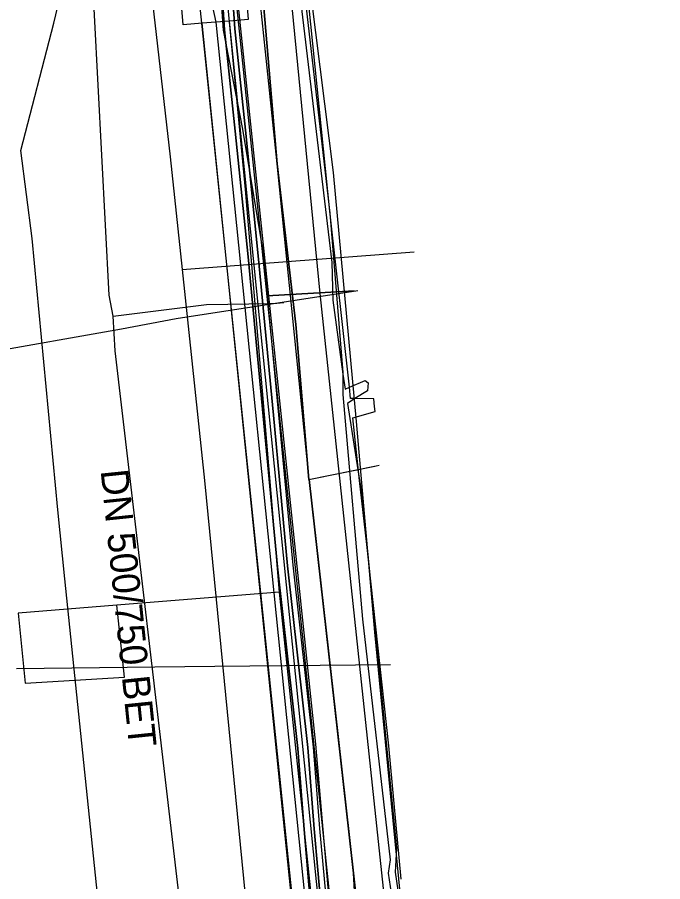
# Model space of a CAD drawing. Extents: x -600309 to -598967, y -1161267 to -1160292.
# Drawn here: x -599156.43 to -599137.72, y -1160334.81 to -1160309.76 of the extents above; entities that cross this region are included whole.
import ezdxf

# ---------------------------------------------------------------- set-up
doc = ezdxf.new("R2010")
doc.units = 0
for name, color, linetype in [('Vrstva 10', 7, 'Continuous'), ('Vrstva 12', 7, 'Continuous'), ('Vrstva 13', 7, 'Continuous'), ('Vrstva 16', 7, 'Continuous'), ('Vrstva 42', 7, 'Continuous'), ('Vrstva 44', 7, 'Continuous'), ('Vrstva 54', 7, 'Continuous'), ('Vrstva 55', 7, 'Continuous'), ('Vrstva 58', 7, 'Continuous'), ('Vrstva 9', 7, 'Continuous')]:
    doc.layers.add(name, color=color, linetype=linetype)

msp = doc.modelspace()

# ---------------------------------------------------------------- linework, layer by layer
at = {"layer": 'Vrstva 10'}
for points in [[(-599152.66, -1160306.2), (-599152.69, -1160305.8), (-599150.08, -1160305.59), (-599149.73, -1160309.82), (-599150.28, -1160309.87)], [(-599151.07, -1160309.93), (-599151.62, -1160309.98), (-599151.8, -1160307.73), (-599152.59, -1160307), (-599152.61, -1160306.75)], [(-599150.28, -1160309.87), (-599151.07, -1160309.93)], [(-599140.7, -1160404.55), (-599150.28, -1160309.87)], [(-599141.4, -1160404.61), (-599151.07, -1160309.93)]]:
    msp.add_lwpolyline(points, dxfattribs=at)
at = {"layer": 'Vrstva 12'}
for points in [[(-599151.44, -1160306.36), (-599150.67, -1160309.9), (-599141.05, -1160404.58), (-599141.12, -1160405.96)], [(-599147.98, -1160323.16), (-599148.35, -1160318.66), (-599148.89, -1160314.01), (-599149.67, -1160306.58)], [(-599147.98, -1160323.16), (-599146.02, -1160322.76), (-599145.94, -1160322.74)], [(-599147.98, -1160323.16), (-599146.69, -1160334.57)], [(-599146.69, -1160334.57), (-599146.63, -1160335.61)]]:
    msp.add_lwpolyline(points, dxfattribs=at)
at = {"layer": 'Vrstva 13'}
for points in [[(-599153.787, -1160295.927), (-599153.482, -1160299.417), (-599153.105, -1160304.16), (-599153.022, -1160304.852), (-599151.992, -1160313.802), (-599151.646, -1160317.07), (-599150.999, -1160323.182), (-599149.825, -1160335.213), (-599149.473, -1160338.732), (-599148.636, -1160347.089), (-599147.954, -1160353.159), (-599147.238, -1160360.509), (-599146.807, -1160364.97), (-599146.176, -1160371.033), (-599145.433, -1160378.125), (-599143.657, -1160395.093), (-599143.103, -1160401.117), (-599142.921, -1160402.361), (-599142.679, -1160404.01), (-599144.473, -1160407.034), (-599142.877, -1160426.561)], [(-599151.646, -1160317.07), (-599151.4, -1160317.051), (-599144.921, -1160316.559)]]:
    msp.add_lwpolyline(points, dxfattribs=at)
at = {"layer": 'Vrstva 16'}
for points in [[(-599147.21, -1160376.02), (-599147.47, -1160373.8), (-599149.64, -1160353.99), (-599149.67, -1160353.23), (-599149.85, -1160352.21), (-599151.43, -1160337.13), (-599151.65, -1160336.05), (-599151.74, -1160335.16), (-599153.59, -1160319.43), (-599153.65, -1160318.42), (-599153.76, -1160317.81), (-599154.72, -1160299.54), (-599152.95, -1160297.98), (-599152.73, -1160297.71), (-599147.093, -1160292.347)], [(-599153.65, -1160318.42), (-599150.94, -1160318.08), (-599149.1, -1160318.06), (-599149.01, -1160318.06), (-599148.7, -1160318.03)]]:
    msp.add_lwpolyline(points, dxfattribs=at)
at = {"layer": 'Vrstva 42'}
for points in [[(-599147.909, -1160335.706), (-599148.116, -1160333.305), (-599148.299, -1160330.954), (-599148.889, -1160325.685), (-599149.299, -1160321.324), (-599149.739, -1160316.705), (-599150.109, -1160313.065), (-599150.419, -1160310.123), (-599150.541, -1160308.353), (-599150.307, -1160306.898), (-599149.897, -1160305.408), (-599149.671, -1160303.974), (-599149.758, -1160302.868), (-599150.029, -1160301.98), (-599150.661, -1160300.875), (-599150.902, -1160299.819), (-599150.738, -1160298.282), (-599150.299, -1160296.681), (-599149.513, -1160295.331), (-599148.572, -1160293.268), (-599147.982, -1160292.347)], [(-599147.909, -1160335.706), (-599148.116, -1160333.305), (-599148.299, -1160330.954), (-599148.889, -1160325.685), (-599149.299, -1160321.324), (-599149.739, -1160316.705), (-599150.109, -1160313.065), (-599150.419, -1160310.123), (-599150.541, -1160308.353), (-599150.307, -1160306.898), (-599149.897, -1160305.408), (-599149.671, -1160303.974), (-599149.758, -1160302.868), (-599150.029, -1160301.98), (-599150.661, -1160300.875), (-599150.902, -1160299.819), (-599150.738, -1160298.282), (-599150.299, -1160296.681), (-599149.513, -1160295.331), (-599148.572, -1160293.268), (-599147.982, -1160292.347)], [(-599147.982, -1160292.347), (-599148.572, -1160293.268), (-599149.513, -1160295.331), (-599150.299, -1160296.681), (-599150.738, -1160298.282), (-599150.902, -1160299.819), (-599150.661, -1160300.875), (-599150.029, -1160301.98), (-599149.758, -1160302.868), (-599149.671, -1160303.974), (-599149.897, -1160305.408), (-599150.307, -1160306.898), (-599150.541, -1160308.353), (-599150.419, -1160310.123), (-599150.109, -1160313.065), (-599149.739, -1160316.705), (-599149.299, -1160321.324), (-599148.889, -1160325.685), (-599148.299, -1160330.954), (-599148.116, -1160333.305), (-599147.909, -1160335.706)], [(-599147.982, -1160292.347), (-599148.572, -1160293.268), (-599149.513, -1160295.331), (-599150.299, -1160296.681), (-599150.738, -1160298.282), (-599150.902, -1160299.819), (-599150.661, -1160300.875), (-599150.029, -1160301.98), (-599149.758, -1160302.868), (-599149.671, -1160303.974), (-599149.897, -1160305.408), (-599150.307, -1160306.898), (-599150.541, -1160308.353), (-599150.419, -1160310.123), (-599150.109, -1160313.065), (-599149.739, -1160316.705), (-599149.299, -1160321.324), (-599148.889, -1160325.685), (-599148.299, -1160330.954), (-599148.116, -1160333.305), (-599147.909, -1160335.706)], [(-599147.611, -1160335.674), (-599147.818, -1160333.281), (-599148.001, -1160330.926), (-599148.591, -1160325.655), (-599149.001, -1160321.296), (-599149.441, -1160316.675), (-599149.811, -1160313.035), (-599150.121, -1160310.097), (-599150.239, -1160308.367), (-599150.013, -1160306.962), (-599149.603, -1160305.472), (-599149.369, -1160303.986), (-599149.462, -1160302.812), (-599149.751, -1160301.86), (-599150.379, -1160300.765), (-599150.598, -1160299.801), (-599150.442, -1160298.338), (-599150.021, -1160296.799), (-599149.247, -1160295.469), (-599148.308, -1160293.412), (-599147.626, -1160292.347)], [(-599147.611, -1160335.674), (-599147.818, -1160333.281), (-599148.001, -1160330.926), (-599148.591, -1160325.655), (-599149.001, -1160321.296), (-599149.441, -1160316.675), (-599149.811, -1160313.035), (-599150.121, -1160310.097), (-599150.239, -1160308.367), (-599150.013, -1160306.962), (-599149.603, -1160305.472), (-599149.369, -1160303.986), (-599149.462, -1160302.812), (-599149.751, -1160301.86), (-599150.379, -1160300.765), (-599150.598, -1160299.801), (-599150.442, -1160298.338), (-599150.021, -1160296.799), (-599149.247, -1160295.469), (-599148.308, -1160293.412), (-599147.626, -1160292.347)], [(-599147.611, -1160335.674), (-599147.818, -1160333.281), (-599148.001, -1160330.926), (-599148.591, -1160325.655), (-599149.001, -1160321.296), (-599149.441, -1160316.675), (-599149.811, -1160313.035), (-599150.121, -1160310.097), (-599150.239, -1160308.367), (-599150.013, -1160306.962), (-599149.603, -1160305.472), (-599149.369, -1160303.986), (-599149.462, -1160302.812), (-599149.751, -1160301.86), (-599150.379, -1160300.765), (-599150.598, -1160299.801), (-599150.442, -1160298.338), (-599150.021, -1160296.799), (-599149.247, -1160295.469), (-599148.308, -1160293.412), (-599147.626, -1160292.347)], [(-599147.611, -1160335.674), (-599147.818, -1160333.281), (-599148.001, -1160330.926), (-599148.591, -1160325.655), (-599149.001, -1160321.296), (-599149.441, -1160316.675), (-599149.811, -1160313.035), (-599150.121, -1160310.097), (-599150.239, -1160308.367), (-599150.013, -1160306.962), (-599149.603, -1160305.472), (-599149.369, -1160303.986), (-599149.462, -1160302.812), (-599149.751, -1160301.86), (-599150.379, -1160300.765), (-599150.598, -1160299.801), (-599150.442, -1160298.338), (-599150.021, -1160296.799), (-599149.247, -1160295.469), (-599148.308, -1160293.412), (-599147.626, -1160292.347)], [(-599147.626, -1160292.347), (-599148.308, -1160293.412), (-599149.247, -1160295.469), (-599150.021, -1160296.799), (-599150.442, -1160298.338), (-599150.598, -1160299.801), (-599150.379, -1160300.765), (-599149.751, -1160301.86), (-599149.462, -1160302.812), (-599149.369, -1160303.986), (-599149.603, -1160305.472), (-599150.013, -1160306.962), (-599150.239, -1160308.367), (-599150.121, -1160310.097), (-599149.811, -1160313.035), (-599149.441, -1160316.675), (-599149.001, -1160321.296), (-599148.591, -1160325.655), (-599148.001, -1160330.926), (-599147.818, -1160333.281), (-599147.611, -1160335.674)], [(-599147.626, -1160292.347), (-599148.308, -1160293.412), (-599149.247, -1160295.469), (-599150.021, -1160296.799), (-599150.442, -1160298.338), (-599150.598, -1160299.801), (-599150.379, -1160300.765), (-599149.751, -1160301.86), (-599149.462, -1160302.812), (-599149.369, -1160303.986), (-599149.603, -1160305.472), (-599150.013, -1160306.962), (-599150.239, -1160308.367), (-599150.121, -1160310.097), (-599149.811, -1160313.035), (-599149.441, -1160316.675), (-599149.001, -1160321.296), (-599148.591, -1160325.655), (-599148.001, -1160330.926), (-599147.818, -1160333.281), (-599147.611, -1160335.674)], [(-599128.152, -1160492.134), (-599129.551, -1160481.92), (-599137.125, -1160434.955), (-599135.957, -1160431.901), (-599137.933, -1160427.949), (-599138.921, -1160417.351), (-599140.268, -1160401.453), (-599144.131, -1160366.155), (-599148.86, -1160321), (-599150.148, -1160308.582), (-599149.609, -1160305.888), (-599149.325, -1160304.719), (-599149.325, -1160303.167), (-599149.831, -1160301.362), (-599150.444, -1160300.243), (-599150.328, -1160299.062), (-599150.366, -1160298.411), (-599149.928, -1160296.845), (-599149.28, -1160295.612), (-599148.278, -1160293.586), (-599147.515, -1160292.347)], [(-599140.901, -1160292.347), (-599143.56, -1160294.878), (-599146.147, -1160297.339), (-599146.617, -1160297.619), (-599146.852, -1160297.824), (-599147.087, -1160298.029), (-599147.38, -1160299.22), (-599147.537, -1160299.859), (-599147.697, -1160300.265), (-599148.647, -1160302.679), (-599148.651, -1160302.72), (-599148.737, -1160303.549), (-599147.367, -1160315.439), (-599146.987, -1160320.059), (-599146.987, -1160320.102), (-599146.987, -1160320.689), (-599146.417, -1160327.209), (-599145.619, -1160334.181), (-599145.676, -1160334.564), (-599145.446, -1160336.115)], [(-599145.301, -1160334.738), (-599145.654, -1160330.878), (-599146.299, -1160325.04), (-599146.504, -1160323.19), (-599146.705, -1160321.367), (-599146.052, -1160321.184), (-599146.072, -1160321.036), (-599146.093, -1160320.823), (-599146.64, -1160320.812), (-599146.766, -1160320.809), (-599146.802, -1160320.483), (-599147.37, -1160315.384), (-599148.651, -1160302.72), (-599148.659, -1160302.638), (-599148.708, -1160302.155), (-599147.962, -1160300.761), (-599147.697, -1160300.265), (-599146.613, -1160298.241), (-599144.118, -1160296.181), (-599141.129, -1160293.456)], [(-599143.659, -1160376.326), (-599144.719, -1160366.306), (-599145.619, -1160358.245), (-599146.469, -1160348.087), (-599147.369, -1160339.998), (-599147.909, -1160335.706), (-599148.116, -1160333.305), (-599148.299, -1160330.954), (-599148.889, -1160325.685), (-599149.299, -1160321.324), (-599149.739, -1160316.705), (-599150.109, -1160313.065), (-599150.419, -1160310.123), (-599150.541, -1160308.353), (-599150.307, -1160306.898), (-599149.897, -1160305.408), (-599149.671, -1160303.974), (-599149.758, -1160302.868), (-599150.029, -1160301.98), (-599150.661, -1160300.875), (-599150.902, -1160299.819), (-599150.738, -1160298.282), (-599150.299, -1160296.681)], [(-599143.659, -1160376.326), (-599144.719, -1160366.306), (-599145.619, -1160358.245), (-599146.469, -1160348.087), (-599147.369, -1160339.998), (-599147.909, -1160335.706), (-599148.116, -1160333.305), (-599148.299, -1160330.954), (-599148.889, -1160325.685), (-599149.299, -1160321.324), (-599149.739, -1160316.705), (-599150.109, -1160313.065), (-599150.419, -1160310.123), (-599150.541, -1160308.353), (-599150.307, -1160306.898), (-599149.897, -1160305.408), (-599149.671, -1160303.974), (-599149.758, -1160302.868), (-599150.029, -1160301.98), (-599150.661, -1160300.875), (-599150.902, -1160299.819), (-599150.738, -1160298.282), (-599150.299, -1160296.681)], [(-599151.26, -1160302.62), (-599150.73, -1160305.23), (-599149.82, -1160314.75), (-599148.84, -1160326.42), (-599147.79, -1160336.37)], [(-599148.923, -1160303.356), (-599147.307, -1160316.865), (-599147.276, -1160317.956), (-599146.987, -1160320.102), (-599146.928, -1160320.536), (-599146.802, -1160320.483), (-599146.345, -1160320.291), (-599146.257, -1160320.359), (-599146.278, -1160320.582), (-599146.64, -1160320.812), (-599146.859, -1160320.951), (-599146.504, -1160323.19), (-599146.442, -1160323.578), (-599146.299, -1160325.04), (-599145.439, -1160333.843), (-599145.478, -1160334.534)], [(-599148.84, -1160326.42), (-599153.545, -1160326.799), (-599156.401, -1160327.026), (-599156.196, -1160329.064), (-599153.319, -1160328.882), (-599153.545, -1160326.799)], [(-599145.478, -1160334.534), (-599145.226, -1160336.234), (-599145.231, -1160336.338), (-599145.25, -1160336.756), (-599145.256, -1160336.897), (-599144.187, -1160348.739), (-599142.868, -1160360.405), (-599142.857, -1160360.469), (-599142.772, -1160360.508), (-599142.683, -1160360.515), (-599142.218, -1160360.551), (-599142.127, -1160360.659), (-599142.234, -1160360.751), (-599142.608, -1160360.722), (-599142.656, -1160360.766), (-599142.788, -1160360.888), (-599142.778, -1160360.955), (-599141.837, -1160369.008), (-599141.833, -1160369.057), (-599141.776, -1160369.657), (-599141.767, -1160369.749), (-599141.439, -1160373.019), (-599141.073, -1160376.671)]]:
    msp.add_lwpolyline(points, dxfattribs=at)
at = {"layer": 'Vrstva 44'}
for points in [[(-599143.504, -1160361.058), (-599143.693, -1160357.556), (-599143.96, -1160353.764), (-599145.493, -1160338.003), (-599147.647, -1160317.762), (-599149.065, -1160303.213), (-599146.983, -1160297.549), (-599141.785, -1160293.237), (-599140.836, -1160292.347)], [(-599140.272, -1160292.347), (-599143.53, -1160295.39), (-599145.66, -1160297.2), (-599146.35, -1160297.96), (-599146.73, -1160298.75), (-599146.75, -1160298.77), (-599148.07, -1160302.03), (-599148.46, -1160303.4), (-599148.46, -1160303.89), (-599147.91, -1160309.2), (-599147.27, -1160314.26), (-599146.6, -1160321.48), (-599146.07, -1160327.58), (-599144.89, -1160339.7), (-599144.41, -1160345.21), (-599143.65, -1160352.83), (-599142.87, -1160360), (-599142.13, -1160365.64)]]:
    msp.add_lwpolyline(points, dxfattribs=at)
at = {"layer": 'Vrstva 54'}
for points in [[(-599151.82, -1160318.49), (-599146.56, -1160317.68)], [(-599153.41, -1160318.79), (-599151.82, -1160318.49)], [(-599157.46, -1160319.5), (-599153.41, -1160318.79)], [(-599156.45, -1160328.63), (-599152.44, -1160328.59)], [(-599152.44, -1160328.59), (-599150.7, -1160328.57)], [(-599150.7, -1160328.57), (-599145.61, -1160328.52)]]:
    msp.add_lwpolyline(points, dxfattribs=at)
at = {"layer": 'Vrstva 55'}
for points in [[(-599147.424, -1160292.347), (-599148.623, -1160294.452), (-599147.69, -1160294.68), (-599148.623, -1160294.452), (-599149.881, -1160296.857), (-599150.294, -1160298.366), (-599150.446, -1160299.792), (-599149.959, -1160301.988), (-599149.778, -1160304.106), (-599150.386, -1160306.815), (-599150.585, -1160308.371), (-599150.458, -1160310.131), (-599149.896, -1160313.002), (-599149.291, -1160316.661), (-599149.179, -1160317.836), (-599146.663, -1160317.692)], [(-599146.663, -1160317.692), (-599149.179, -1160317.836), (-599148.442, -1160325.639), (-599147.851, -1160330.912), (-599147.668, -1160333.268), (-599147.395, -1160336.189), (-599145.94, -1160336.08), (-599144.267, -1160335.954)]]:
    msp.add_lwpolyline(points, dxfattribs=at)
at = {"layer": 'Vrstva 58'}
msp.add_line((-599147.97, -1160323.16), (-599146.57, -1160335.6), dxfattribs=at)
for points in [[(-599092.6, -1160792.56), (-599099.731, -1160739.009), (-599103.73, -1160708.98), (-599103.87, -1160707.87), (-599112.249, -1160645.022), (-599115.7, -1160619.14), (-599115.86, -1160618.03), (-599124.956, -1160552.58), (-599126.88, -1160538.74), (-599127.03, -1160537.63), (-599136.901, -1160461.461), (-599139.27, -1160443.18), (-599139.39, -1160442.06), (-599141.8, -1160408.22), (-599141.59, -1160407.07), (-599141.37, -1160406.57), (-599141.17, -1160405.42), (-599151.39, -1160306.94), (-599152.04, -1160306.49), (-599167.08, -1160307.6), (-599167.65, -1160307.58), (-599167.66, -1160307.02), (-599167.93, -1160292.347)], [(-599092.6, -1160792.56), (-599099.731, -1160739.009), (-599103.73, -1160708.98), (-599103.87, -1160707.87), (-599112.249, -1160645.022), (-599115.7, -1160619.14), (-599115.86, -1160618.03), (-599124.956, -1160552.58), (-599126.88, -1160538.74), (-599127.03, -1160537.63), (-599136.901, -1160461.461), (-599139.27, -1160443.18), (-599139.39, -1160442.06), (-599141.8, -1160408.22), (-599141.59, -1160407.07), (-599141.37, -1160406.57), (-599141.17, -1160405.42), (-599151.39, -1160306.94), (-599152.04, -1160306.49), (-599167.08, -1160307.6), (-599167.65, -1160307.58), (-599167.66, -1160307.02), (-599167.93, -1160292.347)], [(-599092.6, -1160792.56), (-599099.731, -1160739.009), (-599103.73, -1160708.98), (-599103.87, -1160707.87), (-599112.249, -1160645.022), (-599115.7, -1160619.14), (-599115.86, -1160618.03), (-599124.956, -1160552.58), (-599126.88, -1160538.74), (-599127.03, -1160537.63), (-599136.901, -1160461.461), (-599139.27, -1160443.18), (-599139.39, -1160442.06), (-599141.8, -1160408.22), (-599141.59, -1160407.07), (-599141.37, -1160406.57), (-599141.17, -1160405.42), (-599151.39, -1160306.94), (-599152.04, -1160306.49), (-599167.08, -1160307.6), (-599167.65, -1160307.58), (-599167.66, -1160307.02), (-599167.93, -1160292.347)], [(-599147.365, -1160292.347), (-599148.232, -1160293.514), (-599149.129, -1160295.471), (-599149.945, -1160296.939), (-599150.271, -1160298.448), (-599150.434, -1160299.631), (-599150.189, -1160300.65), (-599149.781, -1160301.792), (-599149.292, -1160302.73), (-599149.414, -1160304.034), (-599150.148, -1160308.235), (-599147.783, -1160330.825), (-599147.376, -1160335.555), (-599145.908, -1160347.911), (-599145.255, -1160355.332), (-599142.278, -1160382.939), (-599140.81, -1160398.964), (-599140.362, -1160400.962), (-599138.935, -1160417.273), (-599137.875, -1160427.957), (-599136.08, -1160431.912), (-599137.263, -1160435.011), (-599135.55, -1160444.594), (-599131.472, -1160470.651)], [(-599150.81, -1160302.86), (-599150.5, -1160304.04), (-599150.17, -1160304.92), (-599149.55, -1160306.31), (-599148.89, -1160314.01), (-599148.35, -1160318.66), (-599147.98, -1160323.16)], [(-599137.73, -1160416.97), (-599138.23, -1160414.14), (-599139.13, -1160404.58), (-599140.38, -1160393.64), (-599141.67, -1160380.65), (-599142.15, -1160376.35), (-599144.3, -1160356.36), (-599145.91, -1160341.56), (-599146.3, -1160337.96), (-599146.57, -1160335.6), (-599147.97, -1160323.16), (-599148.89, -1160314.01), (-599149.55, -1160306.31), (-599149.89, -1160305.55), (-599150.5, -1160304.04), (-599150.81, -1160302.86)], [(-599147.97, -1160323.16), (-599148.89, -1160314.01), (-599149.55, -1160306.31), (-599149.89, -1160305.55), (-599150.5, -1160304.04), (-599150.81, -1160302.86)], [(-599147.98, -1160323.16), (-599146.06, -1160322.77)], [(-599147.97, -1160323.16), (-599147.13, -1160330.61), (-599146.57, -1160335.6)]]:
    msp.add_lwpolyline(points, dxfattribs=at)
at = {"layer": 'Vrstva 9'}
for points in [[(-599156.326, -1160313.617), (-599155.371, -1160309.927), (-599153.531, -1160302.285), (-599153.452, -1160301.944), (-599153.209, -1160300.902), (-599151.646, -1160294.191), (-599151.216, -1160292.347)], [(-599153.249, -1160343.473), (-599153.871, -1160337.429), (-599155.044, -1160326.038), (-599155.253, -1160324.031), (-599155.996, -1160316.176), (-599156.326, -1160313.617)]]:
    msp.add_lwpolyline(points, dxfattribs=at)

# ---------------------------------------------------------------- texts
at = {"layer": 'Vrstva 12'}
msp.add_text('DN 500/750 BET', height=0.8, rotation=275.8944, dxfattribs=at).set_placement((-599154.012, -1160322.898))

doc.saveas('drawing.dxf')
